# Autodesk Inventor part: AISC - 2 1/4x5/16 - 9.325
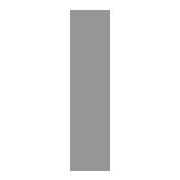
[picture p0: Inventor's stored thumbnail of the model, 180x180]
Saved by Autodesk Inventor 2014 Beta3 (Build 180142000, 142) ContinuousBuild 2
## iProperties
_CCFamilyMember: 149
_CCFamilyDisplayName: ANSI AISC (Rectangular) - Flat Bar Steel
_FrameMemberDoc: Frame Member File
_Version: 15.0.0
_GetPNFromCC: 1
Created: 2010-11
Part Number: AISC - 2 1/4x5/16 - 9.325
Material: Steel, Mild
Description: Flat Bar Steel
Document SubType Name: Modeling
Standard: ANSI
Designer: Beta-8540w
Standards Organization: ANSI
Language: en-US
Size Designation: 2 1/4x5/16
Categories: <MemberInstance><Categories><Category DisplayName="Structural Shapes" InternalName="089c4875-fa83-4c05-b084-43b9cc11f5ed" Mnemonic="GRDR"><CategoryParameter Dis
Stock Number: 2 1/4x5/16
Density: 7.86 g/cm^3
Appearance: Steel
IsCustomPart: 1
G_L: 9.325 in
G_W: 0.313 in
G_H: 2.250 in
Author: Beta-8540w
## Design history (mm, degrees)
node "Start plane"
node "End plane"
node "Driven Length"
  sketch "Sketch3"
    geometry: L1 (0, 0)-(10, 0) reference
    constraints: 2 end point, 1 horizontal
  workplane "Work Plane3"
  sketch "Sketch4"
    geometry: L1 (-2, 0)-(12, 0) reference; L2 (-40.005, 236.864)-(40.005, 236.864) reference
    dimensions: "d9" = 236.86413 distance between parallel lines of L1 L2 (derived)
sketch "Sweep Path"
  geometry: L1 through (-25.4, 40.279) direction (1, 0); L2 through (-112.121, 127) direction (1, 0); 9 other entities
  constraints: 10 horizontal
node "Orientation Work Plane"
feature "Body" dims "d10" = 0
body "Solid1"
sketch "Sketch"
  geometry: L1 (3.969, -28.575)-(-3.969, -28.575); L2 (-3.969, -28.575)-(-3.969, 28.575); L3 (-3.969, 28.575)-(3.969, 28.575); L4 (3.969, 28.575)-(3.969, -28.575); L5 (-6, 0)-(8, 0); L6 (0, -30)-(0, 40); L7 (0, 54)-(0, -44); L8 (-9.2, 0)-(13.2, 0)
  constraints: 16 end point, 2 collinear, 2 parallel, 1 horizontal, 1 perpendicular
  dimensions: "d0" = 57.15 distance between parallel lines of L3 L1 (= G_W); "d1" = 7.9375 distance between parallel lines of L4 L2 (= G_H); "d4" = 3.96875 distance between parallel lines of L6 L4 (= 0.5 x d1); "d5" = 28.575 distance between parallel lines of L5 L3 (= 0.5 x d0)
other parameters: "G_W" = 57.15 [user parameter; used in 1 equation term], "G_H" = 7.9375 [user parameter; used in 1 equation term], "G_L" = 236.86413 (= d9) [user parameter], "G_OFFSET_START" = 0 [user parameter; used in 1 equation term], "G_OFFSET_END" = 0 [user parameter; used in 1 equation term], "d6" = 0 (computed from G_OFFSET_START), "d7" = 236.86413 (= G_OFFSET_END + B_L), "B_L" = 236.86413 [user parameter; used in 1 equation term], "d8" = 90 deg
